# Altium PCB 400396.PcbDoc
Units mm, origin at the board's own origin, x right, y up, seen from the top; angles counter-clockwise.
Board outline 24 x 30 mm, 4 copper layers (Top Layer, Signal Layer 1, Signal Layer 2, Bottom Layer), stack 2.124 mm thick; 4 components, 4 nets, 13 pads, 0 vias.
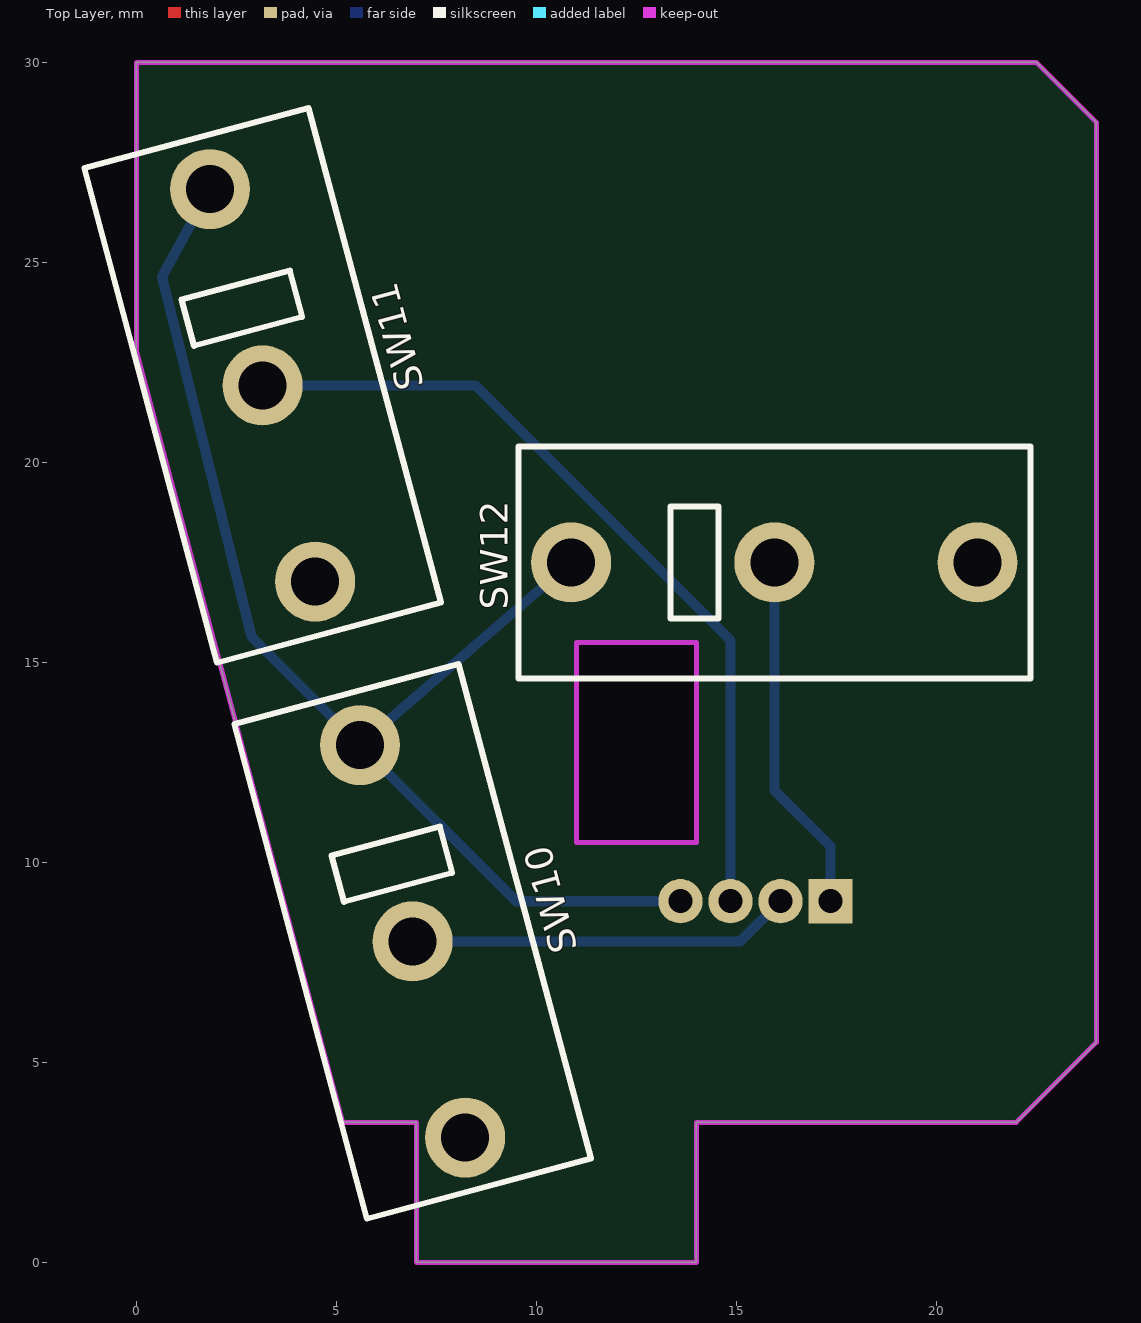
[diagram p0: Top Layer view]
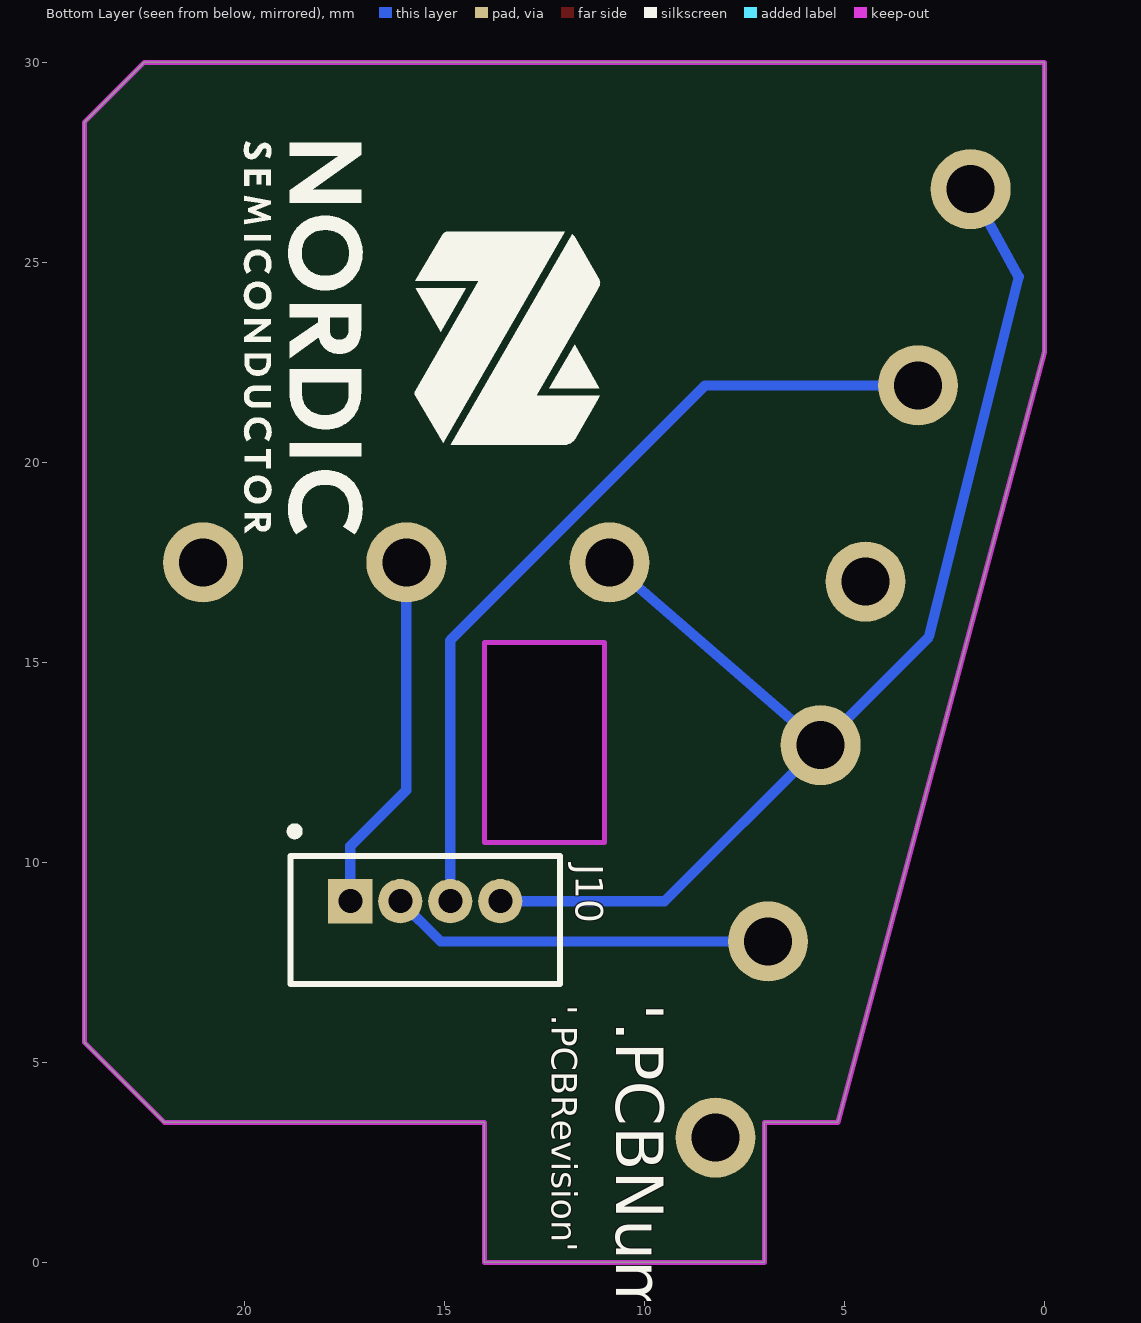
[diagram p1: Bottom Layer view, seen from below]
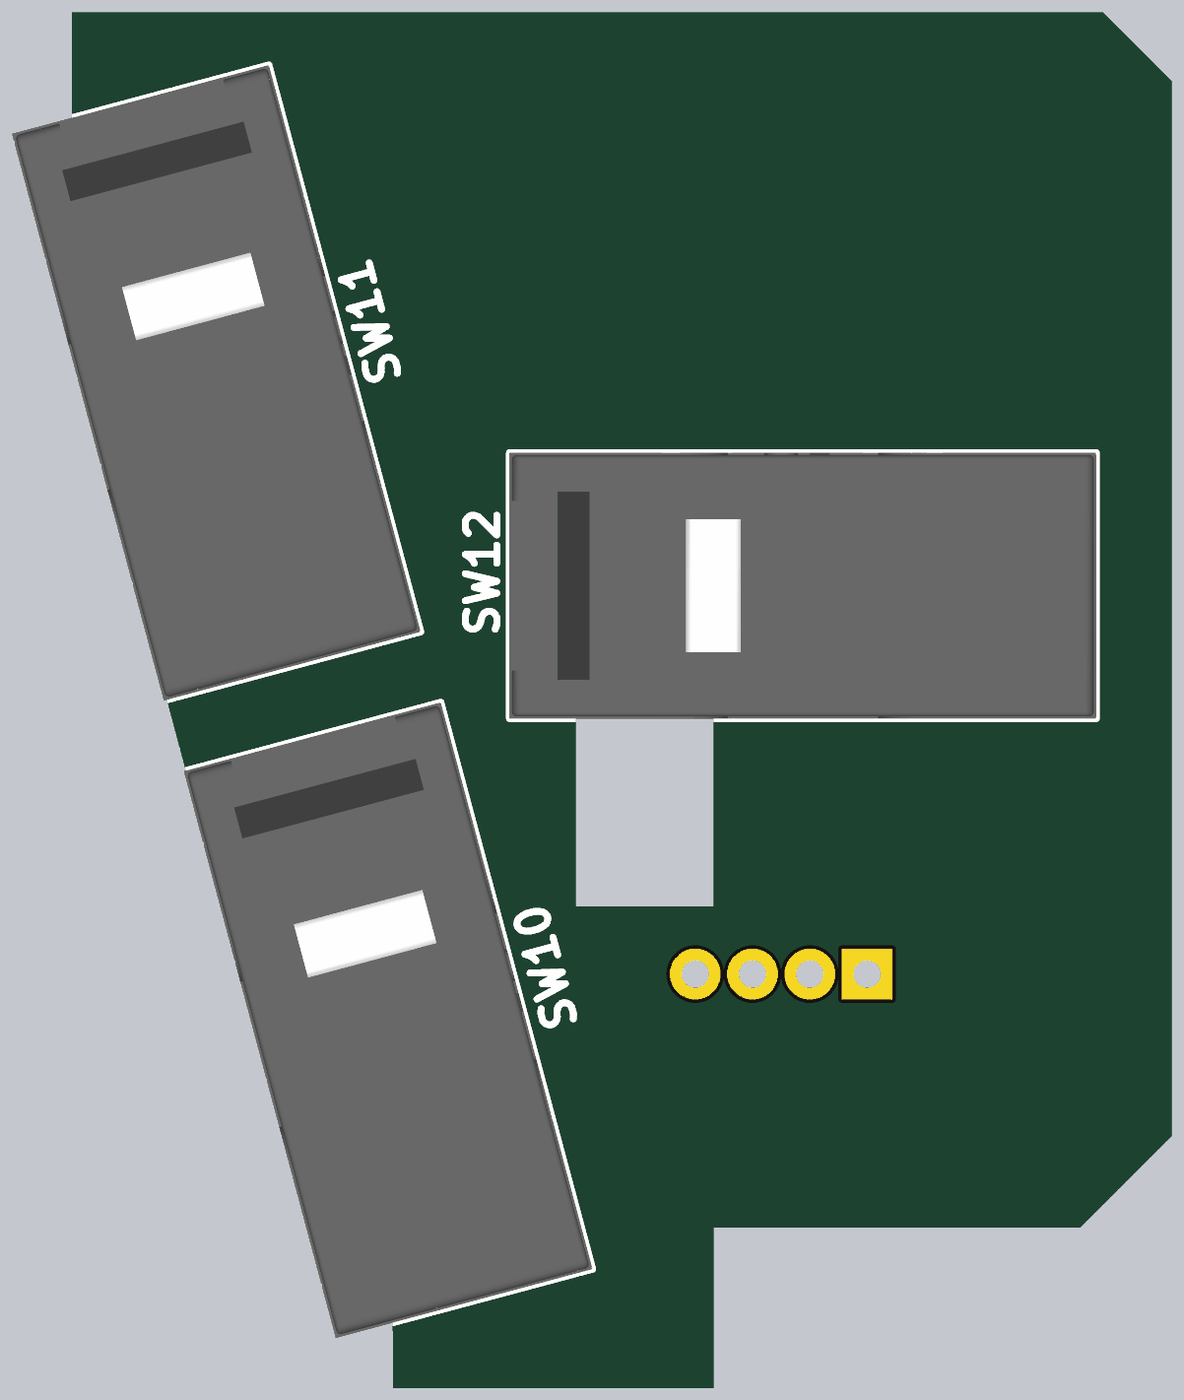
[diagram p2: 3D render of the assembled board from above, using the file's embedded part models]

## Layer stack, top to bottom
Top Solder: solder mask 0.0102, Solder Resist, Dk 3.5
Top Layer: signal copper 0.0356
Dielectric1: core 1.6, FR-4, Dk 4.8
Signal Layer 1: signal copper 0.036
Dielectric 2: prepreg 0.127, Dk 4.2
Signal Layer 2: signal copper 0.036
Dielectric 3: core 0.254, Dk 4.2
Bottom Layer: signal copper 0.0356
Bottom Solder: solder mask 0.0102, Solder Resist, Dk 3.5

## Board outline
5.16,3.5 0,22.758 0,30 22.5,30 24,28.5 24,5.5 22,3.5 14,3.5 14,0 7,0 7,3.5
cut-out: 11,15.5 14,15.5 14,10.5 11,10.5

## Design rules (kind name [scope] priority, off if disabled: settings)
Clearance ANT_Clerance [InNet('ANT')] p1: gap=0.127 ignorepadtopadclearanceinfootprint=FALSE except(0: Arc-Hole Track-Hole SMDPad-Hole THPad-Hole Via-Hole Fill-Hole Poly-Hole Region-Hole Text-Hole)
Clearance Polygon_Clearance [(InNamedPolygon('Top_Layer-GND')) or (InNamedPolygon('Bottom_Layer-GND'))] p2: gap=0.254 ignorepadtopadclearanceinfootprint=FALSE except(0: Arc-Hole Track-Hole SMDPad-Hole THPad-Hole Via-Hole Fill-Hole Poly-Hole Region-Hole Text-Hole)
Clearance [All] p3: gap=0.125 ignorepadtopadclearanceinfootprint=FALSE
ComponentClearance [All] p1 off: gap=0.254 collisioncheckmode=3 verticalgap=0.254 showdistances=FALSE
DiffPairsRouting [All] p1: maxlimit=0.254 minlimit=0.15 mostfreqgap=0.254 toplayer_maxgap=0.15 toplayer_prefgap=0.15 toplayer_minwidth=0.381 toplayer_maxwidth=0.381 toplayer_prefwidth=0.381 midlayer1_mingap=0.254 midlayer1_minwidth=0.381 midlayer1_maxwidth=0.381 midlayer1_prefwidth=0.381 midlayer2_mingap=0.254 midlayer2_minwidth=0.381 midlayer2_maxwidth=0.381 midlayer2_prefwidth=0.381 bottomlayer_maxgap=0.15 bottomlayer_prefgap=0.15 bottomlayer_minwidth=0.381 bottomlayer_maxwidth=0.381 bottomlayer_prefwidth=0.381 maxuncoupledlength=12.7
FabricationTestPointUsage TestPointUsage [All] p1: valid=0 allowmultiple=FALSE
FabricationTestpoint Testpoint [All] p1: side=3 testpointundercomponent=TRUE minsize=1.016 maxsize=2.54 preferedsize=1.524 minholesize=0 maxholesize=1.016 preferedholesize=0.813 testpointgrid=0.025 allowsidetop=TRUE allowsidebottom=TRUE usegrid=TRUE gridtolerance=0
Height [All] p1 off: minheight=0 maxheight=25.4 prefheight=12.7
HoleSize [All] p1: absolutevalues=TRUE maxlimit=5 minlimit=0.305 maxpercent=80.000 minpercent=20.000
MinimumAnnularRing [All] p1 off: minimumring=0.152
PolygonConnect [All] p1: connectstyle=Relief reliefconductorwidth=0.254 reliefentries=4 polygonreliefangle="90 Angle" airgapwidth=0.254
RoutingVias [All] p1: holewidth=0.305 width=0.61 viastyle="Through Hole" minholewidth=0.305 minwidth=0.61 maxholewidth=0.711 maxwidth=1.27
SilkToSolderMaskClearance SilkscreenOverComponentPads [IsPad] p1: minsilkscreentomaskgap=0.254 clearancetoexposedcopper=TRUE
SolderMaskExpansion [All] p1: expansion=0.076
Width [All] p1: maxlimit=2.54 minlimit=0.254 preferedwidth=0.254
23 further rules are at their usual default settings.

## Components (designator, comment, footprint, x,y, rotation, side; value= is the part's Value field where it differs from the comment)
J10 "HDR-4, 1.25mm" 1734598-4 15.477,9.028 r180 bottom
SW10 "SPDT" D2F-F 5.592,12.93 r285 top
SW11 "SPDT" D2F-F 1.842,26.83 r285 top
SW12 "SPDT" D2F-F 10.87,17.5 r0 top

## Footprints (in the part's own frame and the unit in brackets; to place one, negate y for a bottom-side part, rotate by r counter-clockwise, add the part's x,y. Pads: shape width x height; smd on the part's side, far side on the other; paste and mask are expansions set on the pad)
1734598-4 [mm]
  rect 1.108x1.108 hole 0.6: 1(-1.875,0)
  round 1.108 hole 0.6: 2(-0.625,0) 3(0.625,0) 4(1.875,0)
  silkscreen extent -3.37,-2.07 3.37,1.85
D2F-F [mm]
  round 2 hole 1.2: 1(10.16,0) 2(0,0) 3(5.08,0)
  silkscreen extent -1.32,-2.9 11.48,2.9, body extent -1.32,-2.9 11.48,2.9, height 7

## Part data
J10: library part 1734598-4, "Connector Header Through Hole 4 position 0.049\" (1.25mm)", Manufacturer="TE Connectivity", Part number IPS=N.A., Supplier Part Number 1=A99916-ND
SW10 SW11 SW12: library part D2F-F, "SWITCH SNAP ACTION SPDT 1A 125V", Manufacturer=Omron, Part number IPS=N.A., Supplier Part Number 1=SW503-ND

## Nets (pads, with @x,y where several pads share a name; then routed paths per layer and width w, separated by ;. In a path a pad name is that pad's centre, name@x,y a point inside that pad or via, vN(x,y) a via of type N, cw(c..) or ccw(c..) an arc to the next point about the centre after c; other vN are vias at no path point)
BTN_LEFT_PCB_AIM: J10.3 SW11.3 | length 20.9
  Bottom Layer w0.254: SW11.3 8.477,21.923 14.852,15.548 J10.3
BTN_LEFT_PCB_BACK: J10.2 SW10.3 | length 9.6
  Bottom Layer w0.254: SW10.3 15.097,8.023 J10.2
BTN_LEFT_PCB_FRONT: J10.1 SW12.3 | length 9.2
  Bottom Layer w0.254: SW12.3 15.95,11.802 17.352,10.4 J10.1@17.352,8.868
GND: J10.4 SW10.2 SW11.2 SW12.2 | length 32.9
  Top Layer w0.254: SW12.2@10.162,17.5 SW12.2
  Bottom Layer w0.254: SW11.2 0.64,24.64 2.88,15.642 SW10.2 ; SW12.2 SW10.2 ; J10.4 9.494,9.028 SW10.2
pads on no net: SW10.1 SW11.1 SW12.1

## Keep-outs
Keep-Out Layer:
  lines w0.127: 0,22.758 5.16,3.5 7,3.5 7,0 14,0 14,3.5 22,3.5 24,5.5 24,28.5 22.5,30 0,30 0,22.758 ; 11,10.5 14,10.5 14,15.5 11,15.5 11,10.5

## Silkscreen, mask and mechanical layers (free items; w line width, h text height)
Bottom Overlay:
  drawing of 23 lines, arcs and shapes, not listed
  text "'.PCBNumber'" at 11.093,6.482 h2.03 r90
  text "'.PCBRevision'" at 12.312,6.432 h0.64 r90
Board Outline:
  lines w0.152: 0,22.758 0,30 22.5,30 24,28.5 24,5.5 22,3.5 14,3.5 14,0 7,0 7,3.5 5.16,3.5 0,22.758 ; 11,10.5 11,15.5 14,15.5 14,10.5 11,10.5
